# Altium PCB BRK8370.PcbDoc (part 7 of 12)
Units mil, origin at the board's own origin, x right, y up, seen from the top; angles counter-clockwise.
Board outline 8267.72 x 5708.66 mil, 6 copper layers (L1-TOP, L2-GND, L3-PWR, L4-PWR, L5-GND, L6-BOT), stack 68.606 mil thick; 319 components, 516 nets, 2008 pads, 1743 vias.
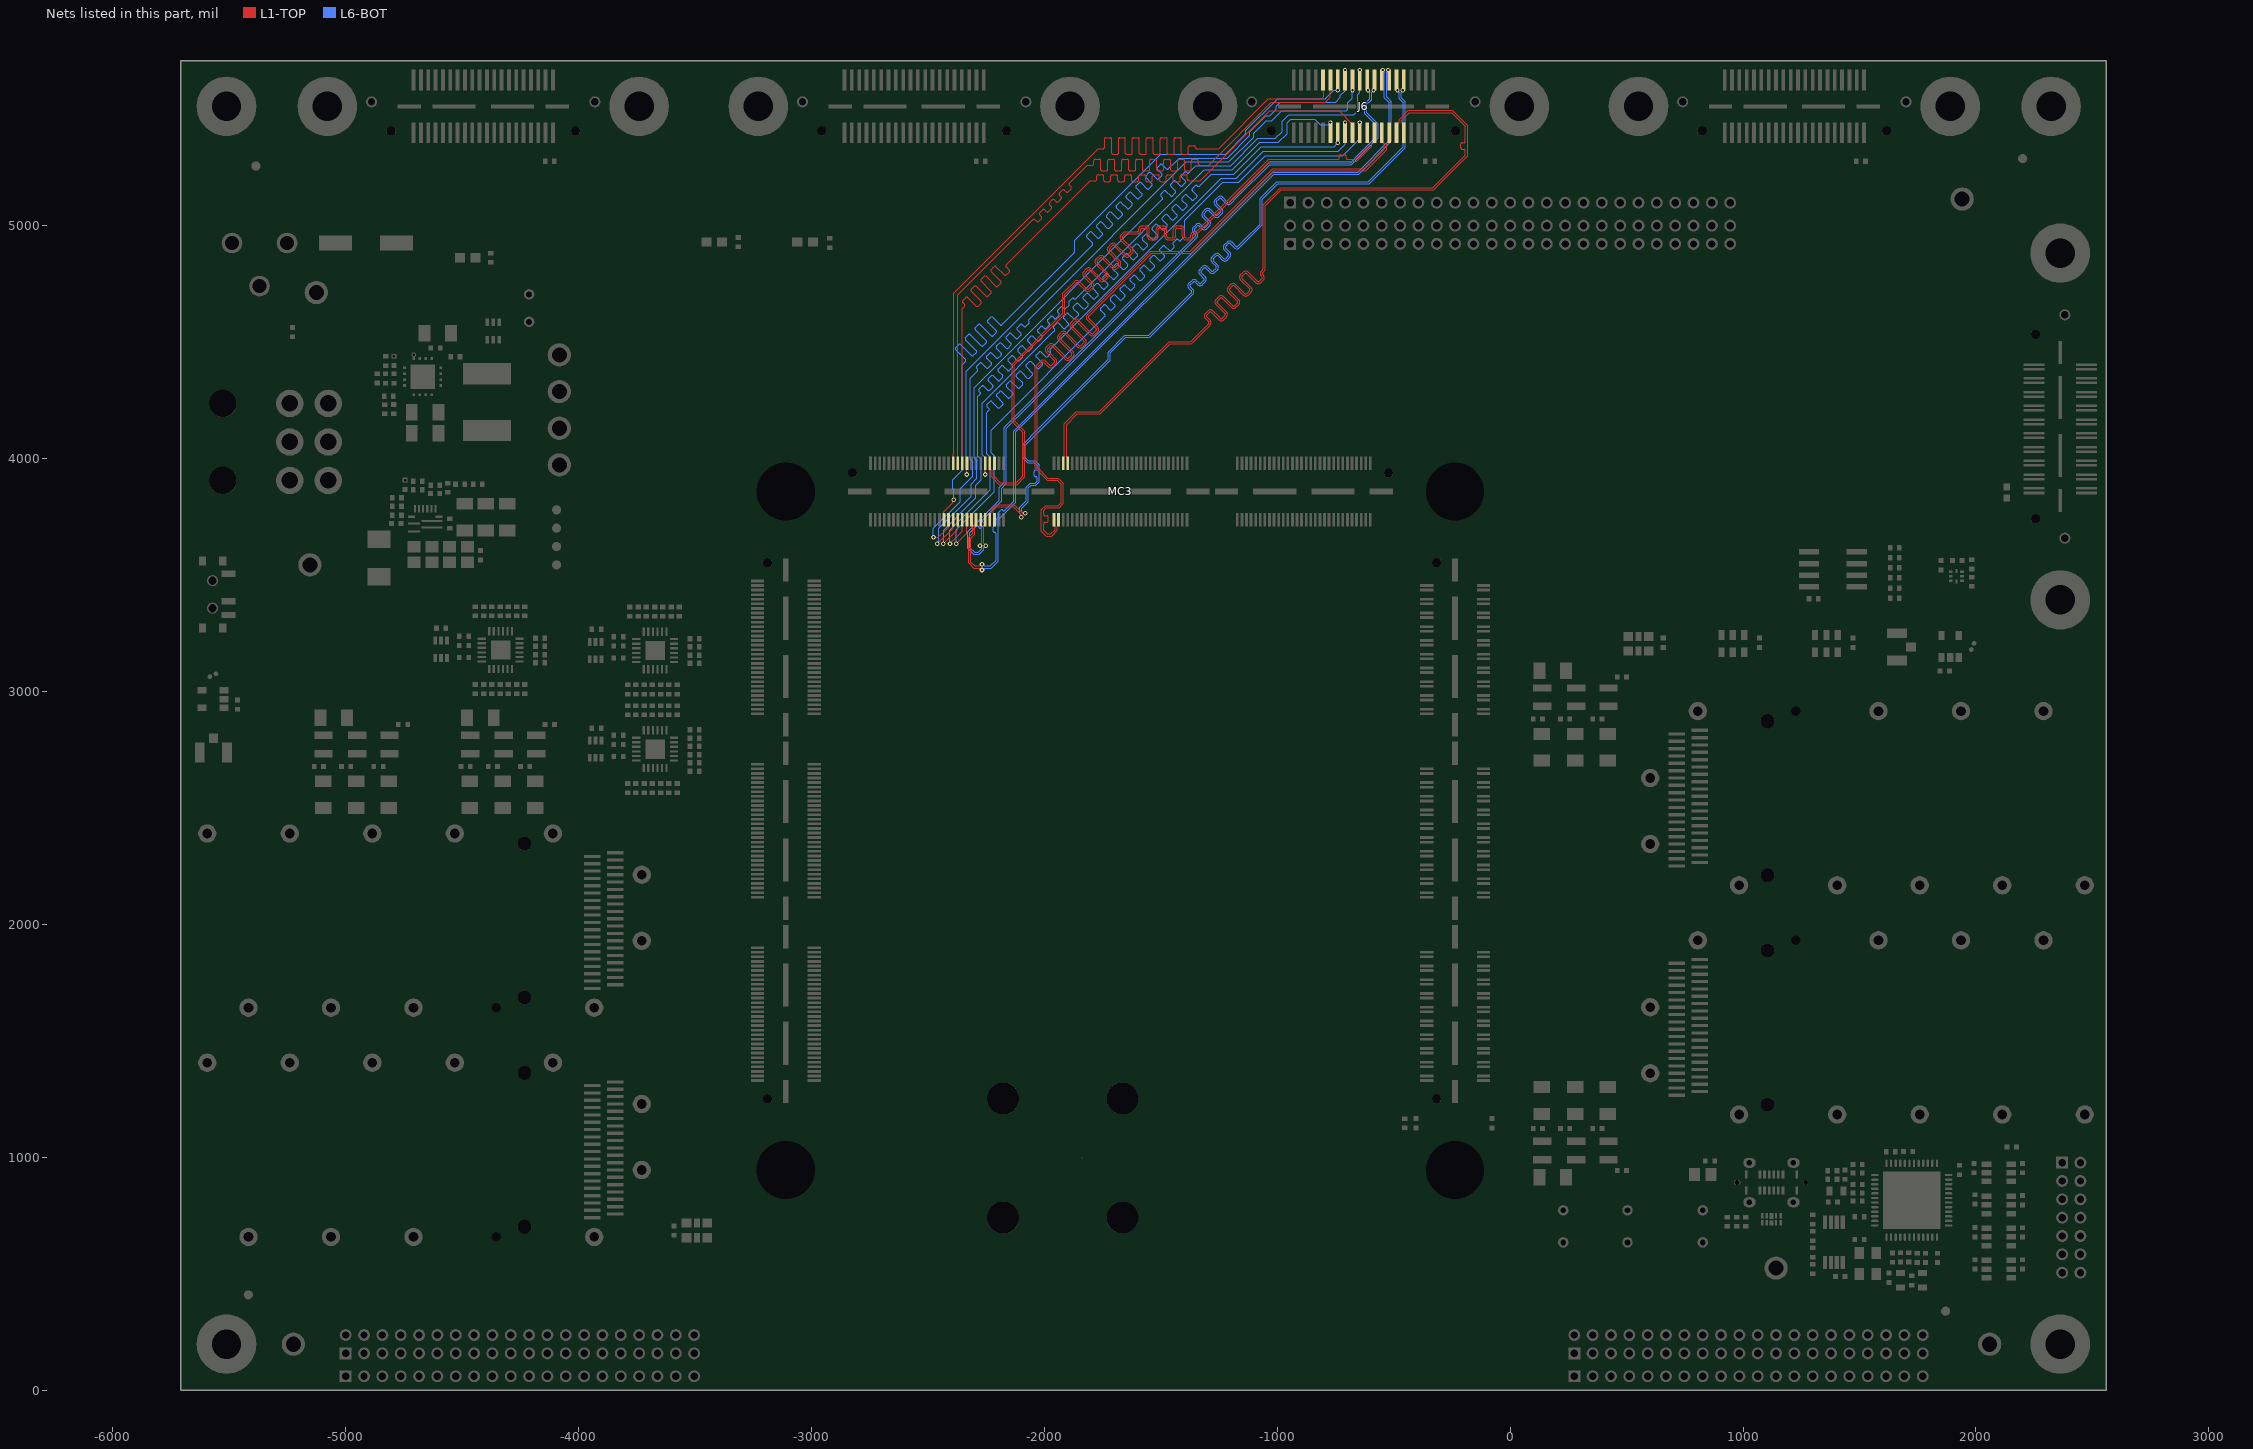
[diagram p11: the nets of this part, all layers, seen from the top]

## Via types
v1: diameter 20, hole 10, L1-TOP to L6-BOT, tented both sides, 957 vias
v2: diameter 18, hole 10, L1-TOP to L6-BOT, tented both sides, 786 vias

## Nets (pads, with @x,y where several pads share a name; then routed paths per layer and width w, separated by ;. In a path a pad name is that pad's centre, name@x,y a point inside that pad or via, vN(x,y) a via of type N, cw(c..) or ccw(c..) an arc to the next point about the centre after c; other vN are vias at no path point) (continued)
PORTC_S4_D2_P: J6.9 MC3.54 | length 3384.1
  L1-TOP w3.3: MC3.54@-2234.25,3736.61 -2234.25,3759.25 -2228.91,3764.59 -2228.91,3781.25 -2208.7,3801.46 -2129.66,3801.46 -2107.96,3779.76 -2094.6,3766.4 -2083.29,3766.4 v1(-2081.67,3764.78)
  L6-BOT w3.3: v1(-2081.67,3764.78) -2083.29,3766.4 -2094.6,3766.4 -2096.62,3768.42 -2096.62,3786.86 -2068.49,3815 -2068.49,3873.81 -2056.6,3885.7 -2036.13,3885.7 -2022.5,3899.33 -2022.5,3972.71 -2039.58,3989.8 -2068.26,3989.8 -2082.68,4004.21 -2082.68,4057.42 -1726.63,4413.47 -1717.64,4422.46 -1717.64,4453.22 -1651.18,4519.68 -1547.9,4519.68 -1523.95,4543.63 -1361.93,4705.65 ccw(c-1372.3,4716.01) -1360.62,4724.87 -1360.62,4725.06 -1361.92,4726.36 -1365.35,4729.79 -1373.12,4737.57 cw(c-1369.12,4741.57) -1373.12,4745.57 -1361.12,4757.58 cw(c-1357.11,4753.58) -1353.11,4757.58 -1341.95,4746.42 ccw(c-1331.56,4756.76) -1321.19,4746.39 -1309.15,4758.43 ccw(c-1319.55,4768.76) -1307.87,4777.62 -1307.87,4777.81 -1326.94,4796.89 cw(c-1322.94,4800.89) -1326.94,4804.89 -1314.93,4816.9 cw(c-1310.93,4812.89) -1306.92,4816.88 ; -1306.9,4816.87 -1289.2,4799.17 ; -1289.2,4799.17 ccw(c-1278.81,4809.51) -1268.44,4799.14 -1256.4,4811.18 ccw(c-1266.8,4821.51) -1255.12,4830.37 -1255.12,4830.56 -1274.19,4849.64 cw(c-1270.19,4853.64) -1274.19,4857.64 -1262.18,4869.65 cw(c-1258.18,4865.64) -1254.17,4869.63 ; -1254.15,4869.62 -1236.45,4851.92 ; -1236.45,4851.92 ccw(c-1226.06,4862.26) -1215.69,4851.89 -1203.65,4863.93 ccw(c-1214.05,4874.26) -1202.37,4883.12 -1202.37,4883.31 -1221.44,4902.39 cw(c-1217.44,4906.39) -1221.44,4910.39 -1209.43,4922.4 cw(c-1205.43,4918.39) -1201.42,4922.38 ; -1201.4,4922.37 -1183.67,4904.64 ccw(c-1173.31,4915.01) -1162.94,4904.64 -1132.22,4935.37 -1064.86,5002.72 -1064.86,5114.06 -998.79,5180.13 -604.76,5180.13 -450.59,5334.31 -450.59,5531.67 -467.97,5549.06 -467.97,5571.97 -460.94,5579.01 v2(-460.94,5581.25)
PORTC_S5_D3_P: J6.10 MC3.65 | length 3565.8
  L1-TOP w3.3: MC3.65@-1919.29,3979.92 -1919.29,4002.56 -1913.95,4007.9 -1913.95,4149.04 -1862.2,4200.79 -1763.78,4200.79 -1463.14,4501.42 -1372.59,4501.42 -1370.08,4503.94 -1294.68,4579.34 ccw(c-1298.68,4583.34) -1294.7,4587.36 ; -1294.7,4587.37 -1308.83,4601.5 cw(c-1298.47,4611.86) -1308.83,4622.23 -1296.79,4634.27 cw(c-1286.46,4623.87) -1276.09,4634.24 -1253.98,4612.12 -1244.26,4602.4 ccw(c-1240.26,4606.41) -1236.26,4602.4 -1224.25,4614.41 ccw(c-1228.25,4618.41) -1224.26,4622.43 -1263.47,4661.63 cw(c-1253.13,4672.03) -1263.5,4682.39 -1251.45,4694.44 cw(c-1241.12,4684.03) -1232.27,4695.72 -1232.08,4695.72 -1191.51,4655.15 ccw(c-1187.51,4659.16) -1183.51,4655.15 -1171.5,4667.16 ccw(c-1175.5,4671.16) -1171.51,4675.18 -1210.72,4714.38 cw(c-1200.38,4724.78) -1210.75,4735.14 -1198.7,4747.19 cw(c-1188.37,4736.78) -1179.52,4748.47 -1179.33,4748.47 -1138.76,4707.9 ccw(c-1134.76,4711.91) -1130.76,4707.9 -1118.75,4719.91 ccw(c-1122.75,4723.91) -1118.76,4727.93 -1157.97,4767.13 cw(c-1147.63,4777.53) -1158,4787.89 -1145.95,4799.94 cw(c-1135.62,4789.53) -1126.77,4801.22 -1126.58,4801.22 -1086.01,4760.65 ccw(c-1082.01,4764.66) -1078.01,4760.65 -1066,4772.66 ccw(c-1070,4776.66) -1066.01,4780.68 -1069.31,4783.97 cw(c-1058.94,4794.34) -1069.31,4804.71 -1064.96,4809.06 -1060.18,4813.83 -1060.18,5088.6 -985.94,5162.84 -331.63,5162.84 -191.79,5302.68 -191.79,5320.82 -191.79,5322.47 ccw(c-197.45,5322.47) -197.45,5328.13 -205.9,5328.13 cw(c-205.9,5333.79) -211.56,5333.79 -211.56,5350.77 cw(c-205.9,5350.77) -205.9,5356.43 -197.45,5356.43 ccw(c-197.45,5362.09) -191.79,5362.09 -191.79,5393.7 -191.79,5425.66 -251.5,5485.38 -433.54,5485.38 -467.87,5451.04 -467.87,5444.04 -465.94,5442.11 -462.97,5442.11 -456.62,5435.76 J6.10@-456.62,5399.01
PORTC_S6_D2_N: J6.11 MC3.56 | length 3384
  L1-TOP w3.3: MC3.56@-2214.57,3736.61 -2214.57,3759.25 -2219.91,3764.59 -2219.91,3777.53 -2204.97,3792.46 -2133.39,3792.46 -2111.69,3770.76 -2100.96,3760.04 -2100.96,3748.72 v1(-2099.35,3747.11)
  L6-BOT w3.3: v1(-2099.35,3747.11) -2100.96,3748.72 -2100.96,3760.04 -2105.62,3764.69 -2105.62,3790.59 -2077.49,3818.72 -2077.49,3877.54 -2060.33,3894.7 -2039.85,3894.7 -2031.5,3903.06 -2031.5,3915.13 -2031.5,3916.78 ccw(c-2037.16,3916.78) -2037.16,3922.44 -2038.13,3922.44 cw(c-2038.13,3928.1) -2043.79,3928.1 -2043.79,3945.08 cw(c-2038.13,3945.08) -2038.13,3950.74 -2037.16,3950.74 ccw(c-2037.16,3956.4) -2031.5,3956.4 -2031.5,3965.05 -2031.5,3968.99 -2043.31,3980.8 -2071.99,3980.8 -2091.68,4000.48 -2091.68,4061.15 -2025.23,4127.6 -1726.64,4426.19 -1726.64,4456.95 -1654.9,4528.68 -1551.62,4528.68 -1530.31,4550 -1368.3,4712.01 ccw(c-1372.3,4716.01) -1368.31,4720.03 -1379.49,4731.2 cw(c-1369.12,4741.57) -1379.49,4751.94 -1367.44,4763.98 cw(c-1357.11,4753.58) -1346.75,4763.94 -1338.97,4756.17 -1335.55,4752.75 ccw(c-1331.56,4756.76) -1327.55,4752.76 -1315.55,4764.76 ccw(c-1319.55,4768.76) -1315.56,4772.78 ; -1333.27,4790.49 -1315.58,4772.8 ; -1333.28,4790.5 cw(c-1322.94,4800.89) -1333.3,4811.25 -1321.26,4823.3 cw(c-1310.93,4812.89) -1302.07,4824.58 -1301.88,4824.58 -1282.8,4805.5 ccw(c-1278.81,4809.51) -1274.8,4805.51 -1262.8,4817.51 ccw(c-1266.8,4821.51) -1262.81,4825.53 ; -1280.52,4843.24 -1262.83,4825.55 ; -1280.53,4843.25 cw(c-1270.19,4853.64) -1280.55,4864 -1268.51,4876.05 cw(c-1258.18,4865.64) -1249.32,4877.33 -1249.13,4877.33 -1230.05,4858.25 ccw(c-1226.06,4862.26) -1222.05,4858.26 -1210.05,4870.26 ccw(c-1214.05,4874.26) -1210.06,4878.28 ; -1227.77,4895.99 -1210.08,4878.3 ; -1227.78,4896 cw(c-1217.44,4906.39) -1227.8,4916.75 -1215.76,4928.8 cw(c-1205.43,4918.39) -1196.57,4930.08 -1196.38,4930.08 -1177.31,4911.01 ccw(c-1173.31,4915.01) -1169.3,4911.01 -1138.58,4941.73 -1073.86,5006.45 -1073.86,5117.79 -1002.51,5189.13 -608.49,5189.13 -459.59,5338.04 -459.59,5527.94 -476.97,5545.33 -476.97,5571.97 -484.01,5579.01 v2(-484.01,5581.25)
PORTC_S7_D3_N: J6.12 MC3.67 | length 3565.9
  L1-TOP w3.3: MC3.67@-1899.61,3979.92 -1899.61,4002.56 -1904.95,4007.9 -1904.95,4145.32 -1858.48,4191.79 -1760.05,4191.79 -1459.42,4492.42 -1368.87,4492.42 -1363.71,4497.57 -1288.31,4572.97 ccw(c-1298.68,4583.34) -1287,4592.19 -1287,4592.39 -1288.3,4593.69 ; -1288.31,4593.71 -1292.63,4598.03 -1302.47,4607.86 cw(c-1298.47,4611.86) -1302.47,4615.86 -1290.46,4627.87 cw(c-1286.46,4623.87) -1282.46,4627.87 -1250.65,4596.06 ccw(c-1240.26,4606.41) -1229.89,4596.04 -1217.85,4608.08 ccw(c-1228.25,4618.41) -1216.57,4627.27 -1216.57,4627.46 -1257.14,4668.03 cw(c-1253.13,4672.03) -1257.13,4676.03 -1245.13,4688.04 cw(c-1241.12,4684.03) -1237.11,4688.02 ; -1237.09,4688.01 -1197.9,4648.82 ccw(c-1187.51,4659.16) -1177.14,4648.79 -1165.1,4660.83 ccw(c-1175.5,4671.16) -1163.82,4680.02 -1163.82,4680.21 -1204.39,4720.78 cw(c-1200.38,4724.78) -1204.38,4728.78 -1192.38,4740.79 cw(c-1188.37,4736.78) -1184.36,4740.77 ; -1184.34,4740.76 -1145.15,4701.57 ccw(c-1134.76,4711.91) -1124.39,4701.54 -1112.35,4713.58 ccw(c-1122.75,4723.91) -1111.07,4732.77 -1111.07,4732.96 -1151.64,4773.53 cw(c-1147.63,4777.53) -1151.63,4781.53 -1139.63,4793.54 cw(c-1135.62,4789.53) -1131.61,4793.52 ; -1131.59,4793.51 -1092.4,4754.32 ccw(c-1082.01,4764.66) -1071.64,4754.29 -1059.6,4766.33 ccw(c-1070,4776.66) -1058.32,4785.52 -1058.32,4785.71 -1062.95,4790.34 cw(c-1058.94,4794.34) -1062.95,4798.34 -1058.6,4802.69 -1051.18,4810.11 -1051.18,5084.87 -982.21,5153.84 -327.9,5153.84 -182.79,5298.96 -182.79,5429.39 -247.77,5494.38 -437.26,5494.38 -476.87,5454.77 -476.87,5444.04 -478.8,5442.11 -481.77,5442.11 -488.12,5435.76 J6.12@-488.12,5399.01
PORTC_S8_D4_P: J6.13 MC3.46 | length 3383.9
  L1-TOP w3.3: MC3.46@-2312.99,3736.61 -2312.99,3713.98 -2307.65,3708.63 -2307.65,3679.15 -2325.65,3661.15 -2325.65,3551.65 -2303.49,3529.49 -2278,3529.49 -2270,3521.49 v1(-2267.72,3521.49)
  L6-BOT w3.3: v1(-2267.72,3521.49) -2265.43,3521.49 -2257.43,3529.49 -2227.84,3529.49 -2198.54,3558.8 -2198.54,3735.96 -2152.22,3782.28 -2122.45,3812.05 -2122.45,4113.95 -1015.62,5220.78 -650.73,5220.78 -509.64,5361.87 -509.64,5531.67 -530.87,5552.9 -530.87,5658.69 -523.84,5665.72 v2(-523.84,5667.97)
PORTC_S9_D5_P: J6.14 MC3.62 | length 3567.3
  L1-TOP w3.3: -1966.11,4482.48 ccw(c-1970.12,4478.49) -1974.13,4482.49 -1986.13,4470.48 ccw(c-1982.13,4466.48) -1986.14,4462.48 -1975.21,4451.56 -1950.34,4426.69 cw(c-1960.71,4416.32) -1950.31,4405.99 -1962.35,4393.95 cw(c-1972.71,4404.31) -1983.08,4393.95 -2001.19,4412.06 ccw(c-2005.2,4408.06) -2009.2,4412.06 -2024.23,4397.03 -2030.33,4390.93 -2030.33,3961.81 -1984.72,3916.2 -1941.25,3916.2 -1919.01,3893.96 -1919.01,3806.83 -1936.75,3789.09 -1990.85,3789.09 -2003.45,3776.49 -2003.45,3768.4 -2003.45,3760.4 ccw(c-1997.79,3760.4) -1997.79,3754.74 -1989.34,3754.74 cw(c-1989.34,3749.08) -1983.68,3749.08 -1983.68,3732.1 cw(c-1989.34,3732.1) -1989.34,3726.44 -1997.79,3726.44 ccw(c-1997.79,3720.78) -2003.45,3720.78 -2003.45,3690.83 -1988.66,3676.04 -1971.97,3676.04 -1953.32,3694.7 -1953.32,3708.63 -1958.66,3713.98 MC3.62@-1958.66,3736.61 ; -1966.09,4482.46 -1909.58,4425.95 ccw(c-1899.19,4436.28) -1888.82,4425.92 -1876.78,4437.96 ccw(c-1887.18,4448.29) -1875.49,4457.15 -1875.49,4457.34 -1933.39,4515.23 cw(c-1929.38,4519.23) -1933.38,4523.23 -1921.38,4535.24 cw(c-1917.37,4531.24) -1913.36,4535.23 ; -1913.34,4535.21 -1856.83,4478.7 ccw(c-1846.44,4489.03) -1836.07,4478.67 -1824.03,4490.71 ccw(c-1834.43,4501.04) -1822.74,4509.9 -1822.74,4510.09 -1880.64,4567.98 cw(c-1876.63,4571.98) -1880.63,4575.98 -1868.63,4587.99 cw(c-1864.62,4583.99) -1860.61,4587.98 ; -1860.59,4587.96 -1804.08,4531.45 ccw(c-1793.69,4541.78) -1783.32,4531.42 -1771.28,4543.46 ccw(c-1781.68,4553.79) -1769.99,4562.65 -1769.99,4562.84 -1810.21,4603.05 cw(c-1806.2,4607.05) -1810.21,4611.05 -1805.86,4615.4 -1539.37,4881.89 -1369.14,4881.89 -1015.89,5235.14 -620.62,5235.14 -530.87,5324.89 -530.87,5353.98 -528.94,5355.91 -525.97,5355.91 -519.62,5362.26 J6.14@-519.62,5399.01
PORTC_S10_D4_N: J6.15 MC3.48 | length 3383.9
  L1-TOP w3.3: MC3.48@-2293.31,3736.61 -2293.31,3713.98 -2298.65,3708.63 -2298.65,3675.42 -2316.65,3657.42 -2316.65,3555.38 -2299.77,3538.49 -2278,3538.49 -2270,3546.49 v1(-2267.72,3546.49)
  L6-BOT w3.3: v1(-2267.72,3546.49) -2265.43,3546.49 -2257.43,3538.49 -2231.57,3538.49 -2207.54,3562.53 -2207.54,3675.26 -2207.54,3676.91 ccw(c-2213.2,3676.91) -2213.2,3682.57 -2214.26,3682.57 cw(c-2214.26,3688.23) -2219.92,3688.23 -2219.92,3705.21 cw(c-2214.26,3705.21) -2214.26,3710.87 -2213.2,3710.87 ccw(c-2213.2,3716.53) -2207.54,3716.53 -2207.54,3732.98 -2207.54,3739.69 -2198.75,3748.47 -2197.59,3749.64 ccw(c-2201.59,3753.64) -2197.59,3757.65 -2198.24,3758.3 cw(c-2194.24,3762.3) -2198.24,3766.31 -2186.24,3778.31 cw(c-2182.23,3774.31) -2178.23,3778.31 -2177.58,3777.66 ccw(c-2173.57,3781.66) -2169.57,3777.66 -2158.59,3788.64 -2131.45,3815.77 -2131.45,4117.68 -1019.35,5229.78 -654.45,5229.78 -518.64,5365.59 -518.64,5527.94 -539.87,5549.17 -539.87,5658.69 -546.91,5665.72 v2(-546.91,5667.97)
PORTC_S11_D5_N: J6.16 MC3.64 | length 3567.3
  L1-TOP w3.3: MC3.64@-1938.98,3736.61 -1938.98,3713.98 -1944.32,3708.63 -1944.32,3690.97 -1968.25,3667.04 -1992.38,3667.04 -2012.45,3687.1 -2012.45,3780.21 -1994.57,3798.09 -1940.48,3798.09 -1928.01,3810.56 -1928.01,3890.23 -1944.98,3907.2 -1988.45,3907.2 -2039.33,3958.08 -2039.33,4394.66 -2030.6,4403.39 -2015.56,4418.43 cw(c-2005.2,4408.06) -1994.83,4418.43 -1976.72,4400.31 ccw(c-1972.71,4404.31) -1968.71,4400.31 -1956.71,4412.32 ccw(c-1960.71,4416.32) -1956.71,4420.32 -1992.47,4456.09 cw(c-1982.13,4466.48) -1992.5,4476.85 -1980.45,4488.89 cw(c-1970.12,4478.49) -1961.27,4490.17 -1961.08,4490.17 -1903.18,4432.28 ccw(c-1899.19,4436.28) -1895.18,4432.28 -1883.18,4444.29 ccw(c-1887.18,4448.29) -1883.19,4452.3 ; -1883.21,4452.32 -1939.72,4508.84 cw(c-1929.38,4519.23) -1939.75,4529.6 -1927.7,4541.64 cw(c-1917.37,4531.24) -1908.52,4542.92 -1908.33,4542.92 -1850.43,4485.03 ccw(c-1846.44,4489.03) -1842.43,4485.03 -1830.43,4497.04 ccw(c-1834.43,4501.04) -1830.44,4505.05 ; -1830.46,4505.07 -1886.97,4561.59 cw(c-1876.63,4571.98) -1887,4582.35 -1874.95,4594.39 cw(c-1864.62,4583.99) -1855.77,4595.67 -1855.58,4595.67 -1797.68,4537.78 ccw(c-1793.69,4541.78) -1789.68,4537.78 -1777.68,4549.79 ccw(c-1781.68,4553.79) -1777.69,4557.8 ; -1777.71,4557.82 -1816.57,4596.69 cw(c-1806.2,4607.05) -1816.57,4617.42 -1812.22,4621.77 -1543.1,4890.89 -1372.87,4890.89 -1019.61,5244.14 -624.35,5244.14 -539.87,5328.62 -539.87,5353.98 -541.8,5355.91 -544.77,5355.91 -551.12,5362.26 J6.16@-551.12,5399.01
PORTC_S12_D6_P: J6.17 MC3.50 | length 3384.2
  L1-TOP w3.3: v1(-2276.28,3625.98) -2276.28,3628.27 -2268.28,3636.27 -2268.28,3665.35 -2268.28,3708.63 -2273.62,3713.98 MC3.50@-2273.62,3736.61
  L6-BOT w3.3: v1(-2276.28,3625.98) -2276.28,3623.7 -2268.28,3615.7 -2268.28,3612.84 -2283.82,3597.3 -2299.68,3597.3 -2320.02,3617.64 -2320.02,3665.35 -2320.02,3681.41 -2314.12,3687.31 -2292.94,3708.49 cw(c-2288.94,3704.48) -2284.94,3708.49 -2278.97,3702.52 ccw(c-2274.97,3706.52) -2270.97,3702.52 -2258.96,3714.52 ccw(c-2262.96,3718.53) -2258.96,3722.53 -2264.93,3728.5 cw(c-2260.93,3732.5) -2264.93,3736.5 -2252.68,3748.75 -2183.68,3817.75 -2183.68,3872.87 -2163.1,3893.44 -2163.1,4055.12 -2163.1,4130.79 -1396.95,4896.95 -1345.57,4948.33 ccw(c-1355.93,4958.69) -1344.25,4967.55 -1344.25,4967.74 -1345.55,4969.04 ; -1345.57,4969.06 -1348.3,4971.79 -1354.53,4978.02 cw(c-1350.53,4982.02) -1354.53,4986.02 -1342.52,4998.03 cw(c-1338.52,4994.03) -1334.52,4998.03 -1323.21,4986.72 ccw(c-1312.82,4997.07) -1302.45,4986.7 -1290.41,4998.74 ccw(c-1300.81,5009.07) -1289.13,5017.93 -1289.13,5018.12 -1313.81,5042.8 cw(c-1309.8,5046.8) -1313.8,5050.8 -1301.8,5062.81 cw(c-1297.8,5058.8) -1293.78,5062.79 ; -1293.76,5062.78 -1270.47,5039.48 ccw(c-1260.07,5049.82) -1249.7,5039.45 -1237.66,5051.49 ccw(c-1248.06,5061.82) -1236.38,5070.68 -1236.38,5070.87 -1261.06,5095.55 cw(c-1257.05,5099.55) -1261.05,5103.55 -1249.05,5115.56 cw(c-1245.05,5111.55) -1241.03,5115.54 ; -1241.01,5115.53 -1220.06,5094.57 ccw(c-1209.69,5104.93) -1199.32,5094.57 -1168.6,5125.29 -1032.46,5261.43 -681.54,5261.43 -634.9,5308.07 -565.8,5377.16 -565.8,5434.29 -615.22,5483.7 -615.22,5520.07 -593.97,5541.32 -593.97,5571.97 -586.94,5579.01 v2(-586.94,5581.25)
PORTC_S13_D7_P: J6.18 MC3.53 | length 3566.7
  L1-TOP w3.3: MC3.53@-2234.25,3979.92 -2234.25,3957.28 -2228.91,3951.94 -2228.91,3923.25 -2193.17,3887.51 -2117.16,3887.51 -2084.16,3920.51 -2084.16,4116.58 -2110.24,4142.65 -2129.92,4162.33 -2129.92,4401.57 -1912.26,4619.24 -1912.26,4704.72 -1902.98,4714 -1863.92,4753.07 cw(c-1859.91,4749.07) -1855.89,4753.05 -1824.76,4721.92 ccw(c-1814.39,4732.29) -1804.03,4721.92 -1791.99,4733.96 ccw(c-1802.39,4744.29) -1792.02,4754.66 -1815.04,4777.68 -1825.15,4787.79 cw(c-1821.15,4791.79) -1825.15,4795.79 -1813.14,4807.8 cw(c-1809.14,4803.79) -1805.13,4807.79 -1761.01,4763.67 ccw(c-1750.61,4774) -1740.25,4763.64 -1728.2,4775.68 ccw(c-1738.61,4786.01) -1726.92,4794.86 -1726.92,4795.06 -1772.4,4840.54 cw(c-1768.4,4844.54) -1772.4,4848.54 -1760.39,4860.55 cw(c-1756.39,4856.54) -1752.38,4860.54 -1708.26,4816.42 ccw(c-1697.86,4826.75) -1687.5,4816.39 -1675.45,4828.43 ccw(c-1685.86,4838.76) -1674.17,4847.61 -1674.17,4847.81 -1719.65,4893.29 cw(c-1715.65,4897.29) -1719.65,4901.29 -1707.64,4913.3 cw(c-1703.64,4909.29) -1699.63,4913.29 -1655.51,4869.17 ccw(c-1645.11,4879.5) -1634.75,4869.14 -1622.7,4881.18 ccw(c-1633.11,4891.51) -1621.42,4900.36 -1621.42,4900.56 -1664.92,4944.06 cw(c-1660.92,4948.06) -1664.92,4952.06 -1660.57,4956.41 -1652.42,4964.57 -1629.92,4964.57 -1600.75,4964.57 ccw(c-1600.75,4979.23) -1586.09,4979.23 -1586.09,4983.91 cw(c-1580.43,4983.91) -1580.43,4989.57 -1563.45,4989.57 cw(c-1563.45,4983.91) -1557.79,4983.91 -1557.79,4954.23 ccw(c-1543.13,4954.23) -1543.13,4939.57 -1526.15,4939.57 ccw(c-1526.15,4954.23) -1511.49,4954.23 -1511.49,4983.91 cw(c-1505.83,4983.91) -1505.83,4989.57 -1488.85,4989.57 cw(c-1488.85,4983.91) -1483.19,4983.91 -1483.19,4954.23 ccw(c-1468.53,4954.23) -1468.53,4939.57 -1451.55,4939.57 ccw(c-1451.55,4954.23) -1436.89,4954.23 -1436.89,4983.91 cw(c-1431.23,4983.91) -1431.23,4989.57 -1414.25,4989.57 cw(c-1414.25,4983.91) -1408.59,4983.91 -1408.59,4954.23 ccw(c-1393.93,4954.23) -1393.93,4939.57 -1376.95,4939.57 ccw(c-1376.95,4954.23) -1362.29,4954.23 -1362.29,4958.91 cw(c-1356.63,4958.91) -1356.63,4964.57 -1350.48,4964.57 -1343.95,4964.57 -1032.72,5275.79 -658.71,5275.79 -593.87,5340.63 -593.87,5353.98 -591.94,5355.91 -588.97,5355.91 -582.62,5362.26 J6.18@-582.62,5399.01
PORTC_S14_D6_N: J6.19 MC3.52 | length 3384.2
  L1-TOP w3.3: MC3.52@-2253.94,3736.61 -2253.94,3713.98 -2259.28,3708.63 -2259.28,3665.35 -2259.28,3636.27 -2251.28,3628.27 v1(-2251.28,3625.98)
  L6-BOT w3.3: v1(-2251.28,3625.98) -2251.28,3623.7 -2259.28,3615.7 -2259.28,3609.11 -2280.09,3588.3 -2303.41,3588.3 -2329.02,3613.92 -2329.02,3665.35 -2329.02,3685.13 -2192.68,3821.48 -2192.68,3876.6 -2172.1,3897.17 -2172.1,4055.12 -2172.1,4134.52 -1403.31,4903.31 -1351.93,4954.69 ccw(c-1355.93,4958.69) -1351.95,4962.71 ; -1351.96,4962.72 -1360.89,4971.66 cw(c-1350.53,4982.02) -1360.89,4992.39 -1348.85,5004.43 cw(c-1338.52,4994.03) -1328.15,5004.4 -1320.28,4996.52 -1316.82,4993.06 ccw(c-1312.82,4997.07) -1308.82,4993.06 -1296.81,5005.07 ccw(c-1300.81,5009.07) -1296.82,5013.09 ; -1296.84,5013.1 -1320.14,5036.4 cw(c-1309.8,5046.8) -1320.17,5057.16 -1308.12,5069.21 cw(c-1297.8,5058.8) -1288.94,5070.49 -1288.75,5070.49 -1264.07,5045.81 ccw(c-1260.07,5049.82) -1256.07,5045.81 -1244.06,5057.82 ccw(c-1248.06,5061.82) -1244.07,5065.84 ; -1244.09,5065.85 -1267.39,5089.15 cw(c-1257.05,5099.55) -1267.42,5109.91 -1255.37,5121.96 cw(c-1245.05,5111.55) -1236.19,5123.24 -1236,5123.24 -1213.69,5100.93 ccw(c-1209.69,5104.93) -1205.69,5100.93 -1174.96,5131.66 -1036.19,5270.43 -685.26,5270.43 -647.62,5308.07 -574.8,5380.89 -574.8,5430.56 -624.22,5479.98 -624.22,5523.8 -602.97,5545.04 -602.97,5571.97 -610.01,5579.01 v2(-610.01,5581.25)
PORTC_S15_D7_N: J6.20 MC3.55 | length 3566.7
  L1-TOP w3.3: MC3.55@-2214.57,3979.92 -2214.57,3957.28 -2219.91,3951.94 -2219.91,3926.98 -2189.44,3896.51 -2120.89,3896.51 -2093.16,3924.24 -2093.16,4112.85 -2110.24,4129.92 -2138.92,4158.61 -2138.92,4405.3 -1921.26,4622.96 -1921.26,4708.45 -1909.34,4720.37 -1870.28,4759.43 cw(c-1859.91,4749.07) -1851.06,4760.75 -1850.86,4760.75 -1849.56,4759.45 ; -1849.55,4759.43 -1840.04,4749.93 -1818.4,4728.28 ccw(c-1814.39,4732.29) -1810.39,4728.28 -1798.39,4740.29 ccw(c-1802.39,4744.29) -1798.39,4748.29 -1831.49,4781.4 cw(c-1821.15,4791.79) -1831.51,4802.15 -1819.47,4814.2 cw(c-1809.14,4803.79) -1800.29,4815.48 -1800.09,4815.48 -1754.61,4770 ccw(c-1750.61,4774) -1746.61,4770 -1734.6,4782.01 ccw(c-1738.61,4786.01) -1734.61,4790.02 -1778.73,4834.14 ; -1778.74,4834.15 cw(c-1768.4,4844.54) -1778.76,4854.9 -1766.72,4866.95 cw(c-1756.39,4856.54) -1747.54,4868.23 -1747.34,4868.23 -1701.86,4822.75 ccw(c-1697.86,4826.75) -1693.86,4822.75 -1681.85,4834.76 ccw(c-1685.86,4838.76) -1681.86,4842.77 -1725.98,4886.89 ; -1725.99,4886.9 cw(c-1715.65,4897.29) -1726.01,4907.65 -1713.97,4919.7 cw(c-1703.64,4909.29) -1694.79,4920.98 -1694.59,4920.98 -1649.11,4875.5 ccw(c-1645.11,4879.5) -1641.11,4875.5 -1629.1,4887.51 ccw(c-1633.11,4891.51) -1629.11,4895.52 -1671.29,4937.69 cw(c-1660.92,4948.06) -1671.29,4958.43 -1666.94,4962.78 -1656.15,4973.57 -1629.92,4973.57 -1600.75,4973.57 ccw(c-1600.75,4979.23) -1595.09,4979.23 -1595.09,4983.91 cw(c-1580.43,4983.91) -1580.43,4998.57 -1563.45,4998.57 cw(c-1563.45,4983.91) -1548.79,4983.91 -1548.79,4954.23 ccw(c-1543.13,4954.23) -1543.13,4948.57 -1526.15,4948.57 ccw(c-1526.15,4954.23) -1520.49,4954.23 -1520.49,4983.91 cw(c-1505.83,4983.91) -1505.83,4998.57 -1488.85,4998.57 cw(c-1488.85,4983.91) -1474.19,4983.91 -1474.19,4954.23 ccw(c-1468.53,4954.23) -1468.53,4948.57 -1451.55,4948.57 ccw(c-1451.55,4954.23) -1445.89,4954.23 -1445.89,4983.91 cw(c-1431.23,4983.91) -1431.23,4998.57 -1414.25,4998.57 cw(c-1414.25,4983.91) -1399.59,4983.91 -1399.59,4954.23 ccw(c-1393.93,4954.23) -1393.93,4948.57 -1376.95,4948.57 ccw(c-1376.95,4954.23) -1371.29,4954.23 -1371.29,4958.91 cw(c-1356.63,4958.91) -1356.63,4973.57 -1350.48,4973.57 -1347.68,4973.57 -1036.45,5284.79 -775.59,5284.79 -738.64,5284.79 ccw(c-738.64,5290.45) -732.98,5290.45 -732.98,5298.9 cw(c-727.32,5298.9) -727.32,5304.56 -710.34,5304.56 cw(c-710.34,5298.9) -704.68,5298.9 -704.68,5290.45 ccw(c-699.02,5290.45) -699.02,5284.79 -669.07,5284.79 -662.44,5284.79 -602.87,5344.36 -602.87,5353.98 -604.8,5355.91 -607.77,5355.91 -614.12,5362.26 J6.20@-614.12,5399.01
PORTC_S16: J6.21 MC3.38 | length 3382.7
  L1-TOP w4.96: v1(-2460.63,3633.86) -2458.97,3633.86 -2391.73,3701.1 MC3.38@-2391.73,3736.61
  L6-BOT w4.96: v1(-2460.63,3633.86) -2460.63,3635.76 -2452.76,3643.64 -2452.76,3700.42 -2314.96,3838.22 -2314.96,3889.76 -2290.12,3914.6 -2290.12,3990.75 -2291.34,3991.97 -2291.34,3992.13 -2302.12,4002.9 -2302.12,4303.87 -1495.19,5110.79 -1493.43,5112.55 ccw(c-1497.67,5116.79) -1493.43,5121.02 -1499.22,5126.81 cw(c-1494.98,5131.04) -1499.22,5135.28 -1486.51,5147.99 cw(c-1482.27,5143.76) -1478.03,5147.99 -1458.17,5128.13 ccw(c-1453.93,5132.37) -1449.69,5128.13 -1436.98,5140.84 ccw(c-1441.22,5145.08) -1436.98,5149.32 -1456.84,5169.18 cw(c-1452.61,5173.42) -1456.84,5177.66 -1444.13,5190.37 cw(c-1439.89,5186.13) -1435.66,5190.37 -1415.79,5170.51 ccw(c-1411.56,5174.74) -1407.32,5170.51 -1394.61,5183.22 ccw(c-1398.85,5187.46) -1394.61,5191.69 -1410.88,5207.97 cw(c-1406.65,5212.21) -1410.88,5216.45 -1398.17,5229.16 cw(c-1393.93,5224.92) -1389.7,5229.16 -1387.5,5226.96 ccw(c-1383.26,5231.2) -1379.02,5226.96 -1360.08,5245.91 -1349.79,5256.2 -1200.5,5256.2 -1082.68,5374.02 -1007.87,5374.02 -979.47,5402.42 -979.47,5448.57 -951.66,5476.38 -672.13,5476.38 -655.17,5493.33 -655.17,5562.41 -645.72,5571.86 v2(-645.72,5667.97)
PORTC_S17: J6.22 MC3.44 | length 3382.7
  L1-TOP w4.96: v1(-2377.95,3633.86) -2332.68,3679.13 MC3.44@-2332.68,3736.61
  L6-BOT w4.96: v1(-2377.95,3633.86) -2377.95,3694.17 -2215.32,3856.8 -2215.32,4012.07 -2228.35,4025.09 -2228.35,4122.05 -1742.13,4608.27 -1740.37,4610.02 ccw(c-1744.61,4614.26) -1740.37,4618.5 -1758.57,4636.7 cw(c-1754.33,4640.93) -1758.57,4645.17 -1745.86,4657.88 cw(c-1741.62,4653.65) -1737.38,4657.88 -1718.67,4639.17 ccw(c-1714.44,4643.41) -1710.2,4639.17 -1697.49,4651.89 ccw(c-1701.72,4656.12) -1697.49,4660.36 -1716.2,4679.07 cw(c-1711.96,4683.31) -1716.2,4687.54 -1703.48,4700.26 cw(c-1699.25,4696.02) -1695.01,4700.26 -1676.3,4681.55 ccw(c-1672.06,4685.78) -1667.82,4681.55 -1655.11,4694.26 ccw(c-1659.35,4698.5) -1655.11,4702.73 -1673.82,4721.44 cw(c-1669.58,4725.68) -1673.82,4729.92 -1661.11,4742.63 cw(c-1656.87,4738.39) -1652.63,4742.63 -1633.92,4723.92 ccw(c-1629.69,4728.16) -1625.45,4723.92 -1612.74,4736.63 ccw(c-1616.97,4740.87) -1612.74,4745.11 -1631.45,4763.82 cw(c-1627.21,4768.06) -1631.45,4772.29 -1618.73,4785 cw(c-1614.5,4780.77) -1610.26,4785 -1591.55,4766.3 ccw(c-1587.31,4770.53) -1583.08,4766.3 -1570.36,4779.01 ccw(c-1574.6,4783.24) -1570.36,4787.48 -1589.07,4806.19 cw(c-1584.84,4810.43) -1589.07,4814.67 -1576.36,4827.38 cw(c-1572.12,4823.14) -1567.89,4827.38 -1549.18,4808.67 ccw(c-1544.94,4812.91) -1540.7,4808.67 -1527.99,4821.38 ccw(c-1532.23,4825.62) -1527.99,4829.86 -1546.7,4848.57 cw(c-1542.46,4852.8) -1546.7,4857.04 -1533.99,4869.75 cw(c-1529.75,4865.52) -1525.51,4869.75 -1506.8,4851.04 ccw(c-1502.56,4855.28) -1498.33,4851.04 -1485.62,4863.76 ccw(c-1489.85,4867.99) -1485.62,4872.23 -1504.32,4890.94 cw(c-1500.09,4895.18) -1504.32,4899.41 -1491.61,4912.13 cw(c-1487.38,4907.89) -1483.14,4912.13 -1464.43,4893.42 ccw(c-1460.19,4897.65) -1455.95,4893.42 -1443.24,4906.13 ccw(c-1447.48,4910.37) -1443.24,4914.6 -1447.09,4918.45 cw(c-1442.85,4922.69) -1447.09,4926.92 -1434.37,4939.64 cw(c-1430.14,4935.4) -1425.9,4939.64 -1422.57,4936.3 ccw(c-1418.33,4940.54) -1414.09,4936.3 -1407.48,4942.91 -1397.64,4952.76 -1397.64,5023.25 -1234.35,5186.55 -1165.82,5186.55 -1052.12,5300.25 -719.44,5300.25 -645.72,5373.96 v2(-645.72,5442.37)
PORTC_S18: J6.23 MC3.36 | length 3382.7
  L1-TOP w4.96: v1(-2476.38,3661.42) -2455.4,3661.42 -2411.42,3705.4 MC3.36@-2411.42,3736.61
  L6-BOT w4.96: v1(-2476.38,3661.42) -2476.38,3700.79 -2362.2,3814.96 -2362.2,3868.99 -2307.09,3924.11 -2307.09,3983.73 -2319.08,3995.72 -2319.08,4344.14 -2288.8,4374.41 -2287.05,4376.17 ccw(c-2291.29,4380.41) -2287.05,4384.64 -2290.49,4388.08 cw(c-2286.25,4392.32) -2290.49,4396.56 -2277.78,4409.27 cw(c-2273.54,4405.03) -2269.3,4409.27 -2249.24,4389.21 ccw(c-2245,4393.45) -2240.77,4389.21 -2228.05,4401.92 ccw(c-2232.29,4406.16) -2228.05,4410.39 -2248.11,4430.46 cw(c-2243.88,4434.69) -2248.11,4438.93 -2235.4,4451.64 cw(c-2231.17,4447.41) -2226.93,4451.64 -2206.87,4431.58 ccw(c-2202.63,4435.82) -2198.39,4431.58 -2185.68,4444.29 ccw(c-2189.92,4448.53) -2185.68,4452.77 -2205.74,4472.83 cw(c-2201.5,4477.07) -2205.74,4481.31 -2193.03,4494.02 cw(c-2188.79,4489.78) -2184.55,4494.02 -2164.49,4473.96 ccw(c-2160.25,4478.19) -2156.02,4473.96 -2143.3,4486.67 ccw(c-2147.54,4490.91) -2143.3,4495.14 ; -2143.3,4495.14 -2163.37,4515.2 cw(c-2159.13,4519.44) -2163.37,4523.68 -2150.65,4536.39 cw(c-2146.42,4532.15) -2142.18,4536.39 -2122.12,4516.33 ccw(c-2117.88,4520.57) -2113.64,4516.33 -2100.93,4529.04 ccw(c-2105.17,4533.28) -2100.93,4537.52 -2116.44,4553.03 cw(c-2112.2,4557.26) -2116.44,4561.5 -2103.73,4574.21 cw(c-2099.49,4569.98) -2095.25,4574.21 -2087.89,4566.85 ccw(c-2083.65,4571.09) -2079.42,4566.85 -2066.7,4579.56 ccw(c-2070.94,4583.8) -2066.7,4588.04 cw(c-2062.47,4592.28) -2066.7,4596.51 -2021.57,4641.65 -1390.06,5273.16 -1207.52,5273.16 -1100.58,5380.1 -1100.58,5395.49 -1046.72,5449.34 -1022.67,5449.34 -979.88,5492.13 -704.72,5492.13 -696.85,5500 -696.85,5527.56 -677.22,5547.19 v2(-677.22,5581.25)
PORTC_S19: J6.24 MC3.41 | length 3564.2
  L1-TOP w4.96: MC3.41@-2352.36,3979.92 -2352.36,4643.7 -2344.39,4651.68 -2342.63,4653.43 ccw(c-2346.87,4657.67) -2342.63,4661.91 -2350.13,4669.41 cw(c-2345.9,4673.65) -2350.13,4677.88 -2337.42,4690.6 cw(c-2333.18,4686.36) -2328.95,4690.6 -2292.92,4654.57 ccw(c-2288.68,4658.81) -2284.45,4654.57 -2271.73,4667.28 ccw(c-2275.97,4671.52) -2271.73,4675.76 -2313.87,4717.89 cw(c-2309.63,4722.13) -2313.87,4726.36 -2301.15,4739.08 cw(c-2296.92,4734.84) -2292.68,4739.08 -2250.55,4696.94 ccw(c-2246.31,4701.18) -2242.07,4696.94 -2229.36,4709.66 ccw(c-2233.6,4713.89) -2229.36,4718.13 -2271.49,4760.26 cw(c-2267.25,4764.5) -2271.49,4768.74 -2258.78,4781.45 cw(c-2254.54,4777.21) -2250.3,4781.45 -2208.17,4739.32 ccw(c-2203.94,4743.56) -2199.7,4739.32 -2186.99,4752.03 ccw(c-2191.22,4756.27) -2186.99,4760.51 -2229.12,4802.64 cw(c-2224.88,4806.87) -2229.12,4811.11 -2216.4,4823.82 cw(c-2212.17,4819.59) -2207.93,4823.82 -2172.14,4788.03 ccw(c-2167.9,4792.27) -2163.66,4788.03 -2150.95,4800.74 ccw(c-2155.19,4804.98) -2150.95,4809.22 -2164.66,4822.93 cw(c-2160.42,4827.17) -2164.66,4831.4 -2129.92,4866.14 -1803.15,5192.91 -1783.86,5192.91 -1781.37,5192.91 ccw(c-1781.37,5198.91) -1775.38,5198.91 -1775.38,5211.92 cw(c-1769.39,5211.92) -1769.39,5217.91 -1751.41,5217.91 cw(c-1751.41,5211.92) -1745.42,5211.92 -1745.42,5195.19 ccw(c-1739.42,5195.19) -1739.42,5189.2 -1721.45,5189.2 ccw(c-1721.45,5195.19) -1715.45,5195.19 -1715.45,5211.92 cw(c-1709.46,5211.92) -1709.46,5217.91 -1691.48,5217.91 cw(c-1691.48,5211.92) -1685.49,5211.92 -1685.49,5195.19 ccw(c-1679.5,5195.19) -1679.5,5189.2 -1661.52,5189.2 ccw(c-1661.52,5195.19) -1655.53,5195.19 -1655.53,5211.92 cw(c-1649.54,5211.92) -1649.54,5217.91 -1631.56,5217.91 cw(c-1631.56,5211.92) -1625.57,5211.92 -1625.57,5195.19 ccw(c-1619.57,5195.19) -1619.57,5189.2 -1601.6,5189.2 ccw(c-1601.6,5195.19) -1595.6,5195.19 -1595.6,5211.92 cw(c-1589.61,5211.92) -1589.61,5217.91 -1571.63,5217.91 cw(c-1571.63,5211.92) -1565.64,5211.92 -1565.64,5195.19 ccw(c-1559.65,5195.19) -1559.65,5189.2 -1541.67,5189.2 ccw(c-1541.67,5195.19) -1535.68,5195.19 -1535.68,5211.92 cw(c-1529.68,5211.92) -1529.68,5217.91 -1511.71,5217.91 cw(c-1511.71,5211.92) -1505.71,5211.92 -1505.71,5195.19 ccw(c-1499.72,5195.19) -1499.72,5189.2 -1481.74,5189.2 ccw(c-1481.74,5195.19) -1475.75,5195.19 -1475.75,5211.92 cw(c-1469.76,5211.92) -1469.76,5217.91 -1451.78,5217.91 cw(c-1451.78,5211.92) -1445.79,5211.92 -1445.79,5195.19 ccw(c-1439.79,5195.19) -1439.79,5189.2 -1421.82,5189.2 ccw(c-1421.82,5195.19) -1415.82,5195.19 -1415.82,5211.92 cw(c-1409.83,5211.92) -1409.83,5217.91 -1391.85,5217.91 cw(c-1391.85,5211.92) -1385.86,5211.92 -1385.86,5198.91 ccw(c-1379.87,5198.91) -1379.87,5192.91 -1337.58,5192.91 -1330.69,5192.91 -1031.48,5492.13 -733.49,5492.13 -677.12,5435.76 J6.24@-677.12,5399.01
PORTC_S20: J6.25 MC3.43 | length 3382.7
  L1-TOP w4.96: v1(-2332.68,3931.1) MC3.43@-2332.68,3979.92
  L6-BOT w4.96: v1(-2332.68,3931.1) -2332.68,3958.66 -2336.04,3962.03 -2336.04,4374.99 -1795.17,4915.87 -1793.41,4917.62 ccw(c-1797.65,4921.86) -1793.41,4926.1 -1817.82,4950.51 cw(c-1813.59,4954.75) -1817.82,4958.98 -1805.11,4971.7 cw(c-1800.87,4967.46) -1796.64,4971.7 -1771.87,4946.93 ccw(c-1767.63,4951.17) -1763.39,4946.93 -1750.68,4959.64 ccw(c-1754.92,4963.88) -1750.68,4968.12 -1775.45,4992.88 cw(c-1771.21,4997.12) -1775.45,5001.36 -1762.74,5014.07 cw(c-1758.5,5009.83) -1754.26,5014.07 -1729.5,4989.3 ccw(c-1725.26,4993.54) -1721.02,4989.3 -1708.31,5002.02 ccw(c-1712.55,5006.25) -1708.31,5010.49 -1733.07,5035.26 cw(c-1728.84,5039.5) -1733.07,5043.73 -1720.36,5056.45 cw(c-1716.13,5052.21) -1711.89,5056.45 -1687.12,5031.68 ccw(c-1682.88,5035.92) -1678.65,5031.68 -1665.93,5044.39 ccw(c-1670.17,5048.63) -1665.93,5052.87 -1690.7,5077.63 cw(c-1686.46,5081.87) -1690.7,5086.11 -1677.99,5098.82 cw(c-1673.75,5094.58) -1669.51,5098.82 -1644.75,5074.05 ccw(c-1640.51,5078.29) -1636.27,5074.05 -1623.56,5086.76 ccw(c-1627.8,5091) -1623.56,5095.24 -1648.33,5120.01 cw(c-1644.09,5124.24) -1648.33,5128.48 -1635.61,5141.19 cw(c-1631.38,5136.96) -1627.14,5141.19 -1602.37,5116.43 ccw(c-1598.14,5120.66) -1593.9,5116.43 -1581.19,5129.14 ccw(c-1585.42,5133.38) -1581.19,5137.61 -1605.95,5162.38 cw(c-1601.72,5166.62) -1605.95,5170.86 -1593.24,5183.57 cw(c-1589,5179.33) -1584.77,5183.57 -1560,5158.8 ccw(c-1555.76,5163.04) -1551.52,5158.8 -1538.81,5171.51 ccw(c-1543.05,5175.75) -1538.81,5179.99 -1563.58,5204.75 cw(c-1559.34,5208.99) -1563.58,5213.23 -1550.87,5225.94 cw(c-1546.63,5221.7) -1542.39,5225.94 -1517.62,5201.17 ccw(c-1513.39,5205.41) -1509.15,5201.17 -1496.44,5213.89 ccw(c-1500.68,5218.12) -1496.44,5222.36 -1515.06,5240.98 cw(c-1510.82,5245.22) -1515.06,5249.45 -1502.34,5262.17 cw(c-1498.11,5257.93) -1493.87,5262.17 -1475.61,5243.9 ccw(c-1471.37,5248.14) -1467.13,5243.9 -1436.23,5274.81 -1420.91,5290.12 -1214.55,5290.12 -1117.54,5387.13 -1117.54,5402.51 -1048.67,5471.38 -1031.89,5471.38 -1004.51,5498.77 -1004.51,5513.21 -987.31,5530.41 -749.43,5530.41 -729.08,5550.76 -729.08,5559.04 -708.72,5579.4 v2(-708.72,5667.97)
PORTC_S21: J6.26 MC3.42 | length 3384.6
  L1-TOP w4.96: v1@-2405.51,3631.89 v1(-2405.51,3633.86) -2352.36,3687.01 MC3.42@-2352.36,3736.61
  L6-BOT w4.96: v1(-2405.51,3633.86) -2405.51,3692.38 -2232.28,3865.61 -2232.28,4005.04 -2248.03,4020.79 -2248.03,4196.85 -2240.16,4204.72 -2238.4,4206.48 ccw(c-2242.64,4210.72) -2238.4,4214.95 -2246.52,4223.07 cw(c-2242.28,4227.3) -2246.52,4231.54 -2233.8,4244.25 cw(c-2229.57,4240.02) -2225.33,4244.25 -2199.54,4218.46 ccw(c-2195.3,4222.7) -2191.06,4218.46 -2178.35,4231.18 ccw(c-2182.59,4235.41) -2178.35,4239.65 -2205.09,4266.39 cw(c-2200.85,4270.62) -2205.09,4274.86 -2192.37,4287.57 cw(c-2188.14,4283.34) -2183.9,4287.57 -2157.16,4260.84 ccw(c-2152.93,4265.07) -2148.69,4260.84 -2135.98,4273.55 ccw(c-2140.21,4277.79) -2135.98,4282.02 -2162.71,4308.76 cw(c-2158.48,4313) -2162.71,4317.24 -2150,4329.95 cw(c-2145.76,4325.71) -2141.53,4329.95 -2114.79,4303.21 ccw(c-2110.55,4307.45) -2106.31,4303.21 -2093.6,4315.92 ccw(c-2097.84,4320.16) -2093.6,4324.4 -2120.34,4351.13 cw(c-2116.1,4355.37) -2120.34,4359.61 -2107.63,4372.32 cw(c-2103.39,4368.08) -2099.15,4372.32 -2072.42,4345.59 ccw(c-2068.18,4349.82) -2063.94,4345.59 -2051.23,4358.3 ccw(c-2055.47,4362.53) -2051.23,4366.77 -2077.96,4393.51 cw(c-2073.73,4397.75) -2077.96,4401.98 -2065.25,4414.7 cw(c-2061.01,4410.46) -2056.78,4414.7 -2030.04,4387.96 ccw(c-2025.8,4392.2) -2021.57,4387.96 -2008.85,4400.67 ccw(c-2013.09,4404.91) -2008.85,4409.15 -2035.59,4435.88 cw(c-2031.35,4440.12) -2035.59,4444.36 -2022.88,4457.07 cw(c-2018.64,4452.83) -2014.4,4457.07 -1994.92,4437.59 ccw(c-1990.68,4441.82) -1986.44,4437.59 -1973.73,4450.3 ccw(c-1977.97,4454.54) -1973.73,4458.77 -1975.68,4460.72 cw(c-1971.45,4464.96) -1975.68,4469.2 -1940.94,4503.94 -1241.37,5203.51 -1176.7,5203.51 -1060.27,5319.93 -739.12,5319.93 -708.72,5350.33 v2(-708.72,5442.37)
PORTC_S22: J6.27 MC3.34 | length 3383.5
  L1-TOP w4.96: MC3.34@-2431.1,3736.61 -2431.23,3736.74 -2431.23,3772.01 -2392.45,3810.78 -2392.45,3820.14 v1(-2389.76,3822.83)
  L6-BOT w4.96: v1(-2389.76,3822.83) -2389.76,3866.21 -2393.7,3870.14 -2393.7,3909.45 -2353,3950.15 -2353,4402.9 -2340.55,4415.35 -2338.8,4417.11 ccw(c-2343.03,4421.35) -2338.8,4425.58 -2381.11,4467.9 cw(c-2376.87,4472.14) -2381.11,4476.37 -2368.4,4489.09 cw(c-2364.16,4484.85) -2359.92,4489.09 -2313.11,4442.27 ccw(c-2308.87,4446.51) -2304.63,4442.27 -2291.92,4454.98 ccw(c-2296.16,4459.22) -2291.92,4463.46 -2338.74,4510.27 cw(c-2334.5,4514.51) -2338.74,4518.75 -2326.02,4531.46 cw(c-2321.79,4527.22) -2317.55,4531.46 -2270.73,4484.64 ccw(c-2266.5,4488.88) -2262.26,4484.64 -2249.55,4497.36 ccw(c-2253.78,4501.59) -2249.55,4505.83 -2296.36,4552.65 cw(c-2292.13,4556.88) -2296.36,4561.12 -2283.65,4573.83 cw(c-2279.41,4569.6) -2275.18,4573.83 -2228.36,4527.02 ccw(c-2224.12,4531.25) -2219.88,4527.02 -2207.17,4539.73 ccw(c-2211.41,4543.97) -2207.17,4548.2 -2243.38,4584.41 cw(c-2239.14,4588.65) -2243.38,4592.89 -2230.67,4605.6 cw(c-2226.43,4601.36) -2222.2,4605.6 -2190.49,4573.89 ccw(c-2186.25,4578.13) -2182.01,4573.89 -2139.76,4616.14 -1870.08,4885.83 -1870.08,4937.01 -1500,5307.09 -1221.57,5307.09 -1134.5,5394.16 -1134.5,5409.54 -998.61,5545.43 -793.97,5545.43 -758.14,5581.25 v2(-740.22,5581.25)
PORTC_S23: J6.28 MC3.51 | length 3382.7
  L1-TOP w4.96: v1(-2253.94,3931.1) MC3.51@-2253.94,3979.92
  L6-BOT w4.96: v1(-2253.94,3931.1) -2253.94,4002.7 -2267.72,4016.48 -2267.72,4236.22 -1958.66,4545.28 -1956.91,4547.03 ccw(c-1961.14,4551.27) -1956.91,4555.51 -1960.18,4558.78 cw(c-1955.94,4563.02) -1960.18,4567.25 -1947.47,4579.97 cw(c-1943.23,4575.73) -1938.99,4579.97 -1918.19,4559.16 ccw(c-1913.95,4563.4) -1909.71,4559.16 -1897,4571.87 ccw(c-1901.24,4576.11) -1897,4580.35 -1917.81,4601.15 cw(c-1913.57,4605.39) -1917.81,4609.63 -1905.09,4622.34 cw(c-1900.86,4618.1) -1896.62,4622.34 -1875.81,4601.53 ccw(c-1871.58,4605.77) -1867.34,4601.53 -1854.63,4614.25 ccw(c-1858.86,4618.48) -1854.63,4622.72 -1875.43,4643.53 cw(c-1871.19,4647.76) -1875.43,4652 -1862.72,4664.71 cw(c-1858.48,4660.48) -1854.25,4664.71 -1833.44,4643.91 ccw(c-1829.2,4648.14) -1824.96,4643.91 -1812.25,4656.62 ccw(c-1816.49,4660.86) -1812.25,4665.09 -1833.06,4685.9 cw(c-1828.82,4690.14) -1833.06,4694.38 -1820.35,4707.09 cw(c-1816.11,4702.85) -1811.87,4707.09 -1791.06,4686.28 ccw(c-1786.83,4690.52) -1782.59,4686.28 -1769.88,4698.99 ccw(c-1774.11,4703.23) -1769.88,4707.47 -1790.68,4728.28 cw(c-1786.45,4732.51) -1790.68,4736.75 -1777.97,4749.46 cw(c-1773.73,4745.23) -1769.5,4749.46 -1748.69,4728.66 ccw(c-1744.45,4732.89) -1740.22,4728.66 -1727.5,4741.37 ccw(c-1731.74,4745.61) -1727.5,4749.84 -1748.31,4770.65 cw(c-1744.07,4774.89) -1748.31,4779.12 -1735.6,4791.84 cw(c-1731.36,4787.6) -1727.12,4791.84 -1706.32,4771.03 ccw(c-1702.08,4775.27) -1697.84,4771.03 -1685.13,4783.74 ccw(c-1689.37,4787.98) -1685.13,4792.22 -1705.94,4813.02 cw(c-1701.7,4817.26) -1705.94,4821.5 -1693.22,4834.21 cw(c-1688.99,4829.97) -1684.75,4834.21 ; -1684.75,4834.21 -1663.94,4813.4 ccw(c-1659.7,4817.64) -1655.47,4813.4 -1642.75,4826.12 ccw(c-1646.99,4830.35) -1642.75,4834.59 -1663.56,4855.4 cw(c-1659.32,4859.64) -1663.56,4863.87 -1650.85,4876.58 cw(c-1646.61,4872.35) -1642.37,4876.58 -1621.57,4855.78 ccw(c-1617.33,4860.02) -1613.09,4855.78 -1600.38,4868.49 ccw(c-1604.62,4872.73) -1600.38,4876.96 -1621.19,4897.77 cw(c-1616.95,4902.01) -1621.19,4906.25 -1608.48,4918.96 cw(c-1604.24,4914.72) -1600,4918.96 -1579.19,4898.15 ccw(c-1574.96,4902.39) -1570.72,4898.15 -1558.01,4910.86 ccw(c-1562.24,4915.1) -1558.01,4919.34 -1578.81,4940.15 cw(c-1574.58,4944.38) -1578.81,4948.62 -1566.1,4961.33 cw(c-1561.86,4957.1) -1557.63,4961.33 -1536.82,4940.53 ccw(c-1532.58,4944.76) -1528.34,4940.53 -1515.63,4953.24 ccw(c-1519.87,4957.48) -1515.63,4961.71 -1536.44,4982.52 cw(c-1532.2,4986.76) -1536.44,4990.99 -1523.73,5003.71 cw(c-1519.49,4999.47) -1515.25,5003.71 -1494.45,4982.9 ccw(c-1490.21,4987.14) -1485.97,4982.9 -1473.26,4995.61 ccw(c-1477.5,4999.85) -1473.26,5004.09 -1494.07,5024.89 cw(c-1489.83,5029.13) -1494.07,5033.37 -1481.35,5046.08 cw(c-1477.12,5041.84) -1472.88,5046.08 -1452.07,5025.27 ccw(c-1447.83,5029.51) -1443.6,5025.27 -1430.88,5037.99 ccw(c-1435.12,5042.22) -1430.88,5046.46 -1451.69,5067.27 cw(c-1447.45,5071.51) -1451.69,5075.74 -1438.98,5088.46 cw(c-1434.74,5084.22) -1430.5,5088.46 -1409.7,5067.65 ccw(c-1405.46,5071.89) -1401.22,5067.65 -1388.51,5080.36 ccw(c-1392.75,5084.6) -1388.51,5088.84 -1409.32,5109.64 cw(c-1405.08,5113.88) -1409.32,5118.12 -1396.61,5130.83 cw(c-1392.37,5126.59) -1388.13,5130.83 -1367.32,5110.02 ccw(c-1363.09,5114.26) -1358.85,5110.02 -1346.14,5122.73 ccw(c-1350.37,5126.97) -1346.14,5131.21 -1364.62,5149.69 cw(c-1360.38,5153.93) -1364.62,5158.17 -1351.91,5170.88 cw(c-1347.67,5166.64) -1343.43,5170.88 -1342.48,5169.93 ccw(c-1338.24,5174.17) -1334.01,5169.93 -1297.24,5206.69 -1283.46,5220.47 -1187.57,5220.47 -1068.43,5339.62 -756.26,5339.62 v2(-740.22,5355.65)
PORTC_S24: J6.29 MC3.39 | length 3558.7
  L1-TOP w4.96: MC3.39@-2372.05,3979.92 -2371.33,3980.63 -2371.33,4703.95 -2072.8,5002.49 -2049.86,5025.43 cw(c-2045.62,5021.19) -2041.38,5025.43 -2033.58,5017.62 ccw(c-2029.34,5021.86) -2025.1,5017.62 -2012.39,5030.33 ccw(c-2016.63,5034.57) -2012.39,5038.81 -2020.2,5046.62 cw(c-2015.96,5050.85) -2020.2,5055.09 -2007.48,5067.8 cw(c-2003.25,5063.57) -1999.01,5067.8 -1991.2,5060 ccw(c-1986.96,5064.23) -1982.73,5060 -1970.01,5072.71 ccw(c-1974.25,5076.95) -1970.01,5081.18 -1977.82,5088.99 cw(c-1973.58,5093.23) -1977.82,5097.47 -1965.11,5110.18 cw(c-1960.87,5105.94) -1956.64,5110.18 -1948.83,5102.37 ccw(c-1944.59,5106.61) -1940.35,5102.37 -1927.64,5115.08 ccw(c-1931.88,5119.32) -1927.64,5123.56 -1935.45,5131.37 cw(c-1931.21,5135.6) -1935.45,5139.84 -1922.74,5152.55 cw(c-1918.5,5148.32) -1914.26,5152.55 -1906.45,5144.74 ccw(c-1902.22,5148.98) -1897.98,5144.74 -1885.27,5157.46 ccw(c-1889.5,5161.69) -1885.27,5165.93 -1893.07,5173.74 cw(c-1888.84,5177.98) -1893.07,5182.21 -1840.52,5234.77 -1815.45,5259.84 -1796.26,5259.84 -1793.78,5259.84 ccw(c-1793.78,5265.84) -1787.78,5265.84 -1787.78,5278.85 cw(c-1781.79,5278.85) -1781.79,5284.84 -1763.81,5284.84 cw(c-1763.81,5278.85) -1757.82,5278.85 -1757.82,5240.87 ccw(c-1751.83,5240.87) -1751.83,5234.88 -1733.85,5234.88 ccw(c-1733.85,5240.87) -1727.86,5240.87 -1727.86,5278.85 cw(c-1721.87,5278.85) -1721.87,5284.84 -1703.89,5284.84 cw(c-1703.89,5278.85) -1697.9,5278.85 -1697.9,5240.87 ccw(c-1691.9,5240.87) -1691.9,5234.88 -1673.93,5234.88 ccw(c-1673.93,5240.87) -1667.93,5240.87 -1667.93,5278.85 cw(c-1661.94,5278.85) -1661.94,5284.84 -1643.96,5284.84 cw(c-1643.96,5278.85) -1637.97,5278.85 -1637.97,5240.87 ccw(c-1631.98,5240.87) -1631.98,5234.88 -1614,5234.88 ccw(c-1614,5240.87) -1608.01,5240.87 -1608.01,5278.85 cw(c-1602.01,5278.85) -1602.01,5284.84 -1584.04,5284.84 cw(c-1584.04,5278.85) -1578.04,5278.85 -1578.04,5240.87 ccw(c-1572.05,5240.87) -1572.05,5234.88 -1554.07,5234.88 ccw(c-1554.07,5240.87) -1548.08,5240.87 -1548.08,5278.85 cw(c-1542.09,5278.85) -1542.09,5284.84 -1524.11,5284.84 cw(c-1524.11,5278.85) -1518.12,5278.85 -1518.12,5240.87 ccw(c-1512.13,5240.87) -1512.13,5234.88 -1494.15,5234.88 ccw(c-1494.15,5240.87) -1488.15,5240.87 -1488.15,5278.85 cw(c-1482.16,5278.85) -1482.16,5284.84 -1464.18,5284.84 cw(c-1464.18,5278.85) -1458.19,5278.85 -1458.19,5240.87 ccw(c-1452.2,5240.87) -1452.2,5234.88 -1434.22,5234.88 ccw(c-1434.22,5240.87) -1428.23,5240.87 -1428.23,5278.85 cw(c-1422.24,5278.85) -1422.24,5284.84 -1404.26,5284.84 cw(c-1404.26,5278.85) -1398.27,5278.85 -1398.27,5240.87 ccw(c-1392.27,5240.87) -1392.27,5234.88 -1374.3,5234.88 ccw(c-1374.3,5240.87) -1368.3,5240.87 -1368.3,5278.85 cw(c-1362.31,5278.85) -1362.31,5284.84 -1344.33,5284.84 cw(c-1344.33,5278.85) -1338.34,5278.85 -1338.34,5265.84 ccw(c-1332.35,5265.84) -1332.35,5259.84 -1299.8,5259.84 -1294.82,5259.84 -1025.02,5529.64 -793.19,5529.64 -771.62,5551.21 J6.29@-771.62,5624.61
PORTC_S25: J6.30 MC3.40 | length 3381.7
  L1-TOP w4.96: v1@-2433.98,3634.86 -2372.05,3696.79 MC3.40@-2372.05,3736.61
  L6-BOT w4.96: v1(-2433.98,3633.86) -2433.07,3634.76 -2433.07,3692.91 -2295.28,3830.71 -2295.28,3885.46 -2271.65,3909.08 -2271.65,3996.43 -2285.14,4009.92 -2285.14,4266.28 -2277.68,4273.74 -2275.93,4275.5 ccw(c-2280.16,4279.74) -2275.93,4283.97 -2280.92,4288.96 cw(c-2276.68,4293.2) -2280.92,4297.44 -2268.2,4310.15 cw(c-2263.97,4305.91) -2259.73,4310.15 -2242.99,4293.41 ccw(c-2238.75,4297.65) -2234.51,4293.41 -2221.8,4306.12 ccw(c-2226.04,4310.36) -2221.8,4314.6 -2240.36,4333.16 cw(c-2236.12,4337.4) -2240.36,4341.63 -2227.65,4354.34 cw(c-2223.41,4350.11) -2219.17,4354.34 -2200.62,4335.79 ccw(c-2196.38,4340.02) -2192.14,4335.79 -2179.43,4348.5 ccw(c-2183.67,4352.74) -2179.43,4356.97 -2197.99,4375.53 cw(c-2193.75,4379.77) -2197.99,4384.01 -2185.28,4396.72 cw(c-2181.04,4392.48) -2176.8,4396.72 -2158.24,4378.16 ccw(c-2154,4382.4) -2149.77,4378.16 -2137.05,4390.87 ccw(c-2141.29,4395.11) -2137.05,4399.35 -2155.61,4417.91 cw(c-2151.38,4422.14) -2155.61,4426.38 -2142.9,4439.09 cw(c-2138.66,4434.86) -2134.43,4439.09 -2115.87,4420.53 ccw(c-2111.63,4424.77) -2107.39,4420.53 -2094.68,4433.25 ccw(c-2098.92,4437.48) -2094.68,4441.72 -2113.24,4460.28 cw(c-2109,4464.52) -2113.24,4468.75 -2100.53,4481.47 cw(c-2096.29,4477.23) -2092.05,4481.47 -2073.49,4462.91 ccw(c-2069.26,4467.15) -2065.02,4462.91 -2052.31,4475.62 ccw(c-2056.54,4479.86) -2052.31,4484.09 -2070.87,4502.65 cw(c-2066.63,4506.89) -2070.87,4511.13 -2058.15,4523.84 cw(c-2053.92,4519.6) -2049.68,4523.84 -2031.12,4505.28 ccw(c-2026.88,4509.52) -2022.64,4505.28 -2009.93,4517.99 ccw(c-2014.17,4522.23) -2009.93,4526.47 -2028.49,4545.03 cw(c-2024.25,4549.27) -2028.49,4553.5 -2015.78,4566.22 cw(c-2011.54,4561.98) -2007.3,4566.21 -2000.44,4559.35 ccw(c-1996.2,4563.59) -1991.97,4559.35 -1979.25,4572.06 ccw(c-1983.49,4576.3) -1979.25,4580.54 -1986.12,4587.4 cw(c-1981.88,4591.64) -1986.12,4595.88 -1973.41,4608.59 cw(c-1969.17,4604.35) -1964.93,4608.59 -1958.07,4601.72 ccw(c-1953.83,4605.96) -1949.59,4601.72 -1936.88,4614.44 ccw(c-1941.12,4618.67) -1936.88,4622.91 -1942.23,4628.26 cw(c-1937.99,4632.5) -1942.23,4636.73 -1929.51,4649.45 cw(c-1925.28,4645.21) -1921.04,4649.45 -1915.69,4644.1 ccw(c-1911.45,4648.34) -1907.22,4644.1 -1894.5,4656.81 ccw(c-1898.74,4661.05) -1894.5,4665.29 -1894.56,4665.34 cw(c-1890.32,4669.58) -1894.56,4673.82 -1881.85,4686.53 cw(c-1877.61,4682.29) -1873.37,4686.53 ccw(c-1869.13,4690.76) -1864.9,4686.53 -1839.34,4712.08 -1312.49,5238.93 -1193.76,5238.93 -1075.65,5357.04 -995.1,5357.04 -957.53,5394.62 -957.53,5442.2 -943.04,5456.69 -839.54,5456.69 -815.43,5432.59 -781.5,5432.59 v2(-771.72,5442.37)
PORTC_S26: J6.31 MC3.37 | length 3561.6
  L1-TOP w4.96: MC3.37@-2391.73,3979.92 -2391.73,4017.72 -2389.01,4020.44 -2389.01,4031.37 -2388.88,4031.5 -2388.88,4710.4 -1768.57,5330.71 -1750.03,5330.71 -1747.54,5330.71 ccw(c-1747.54,5336.7) -1741.55,5336.7 -1741.55,5372.06 cw(c-1735.56,5372.06) -1735.56,5378.05 -1717.58,5378.05 cw(c-1717.58,5372.06) -1711.59,5372.06 -1711.59,5311.7 ccw(c-1705.6,5311.7) -1705.6,5305.71 -1687.62,5305.71 ccw(c-1687.62,5311.7) -1681.63,5311.7 -1681.63,5372.06 cw(c-1675.63,5372.06) -1675.63,5378.05 -1657.66,5378.05 cw(c-1657.66,5372.06) -1651.66,5372.06 -1651.66,5311.7 ccw(c-1645.67,5311.7) -1645.67,5305.71 -1627.69,5305.71 ccw(c-1627.69,5311.7) -1621.7,5311.7 -1621.7,5372.06 cw(c-1615.71,5372.06) -1615.71,5378.05 -1597.73,5378.05 cw(c-1597.73,5372.06) -1591.74,5372.06 -1591.74,5311.7 ccw(c-1585.74,5311.7) -1585.74,5305.71 -1567.77,5305.71 ccw(c-1567.77,5311.7) -1561.77,5311.7 -1561.77,5372.06 cw(c-1555.78,5372.06) -1555.78,5378.05 -1537.8,5378.05 cw(c-1537.8,5372.06) -1531.81,5372.06 -1531.81,5311.7 ccw(c-1525.82,5311.7) -1525.82,5305.71 -1507.84,5305.71 ccw(c-1507.84,5311.7) -1501.85,5311.7 -1501.85,5372.06 cw(c-1495.86,5372.06) -1495.86,5378.05 -1477.88,5378.05 cw(c-1477.88,5372.06) -1471.88,5372.06 -1471.88,5311.7 ccw(c-1465.89,5311.7) -1465.89,5305.71 -1447.91,5305.71 ccw(c-1447.91,5311.7) -1441.92,5311.7 -1441.92,5372.06 cw(c-1435.93,5372.06) -1435.93,5378.05 -1417.95,5378.05 cw(c-1417.95,5372.06) -1411.96,5372.06 -1411.96,5311.7 ccw(c-1405.97,5311.7) -1405.97,5305.71 -1387.99,5305.71 ccw(c-1387.99,5311.7) -1382,5311.7 -1382,5336.77 cw(c-1376,5336.77) -1376,5342.76 -1358.03,5342.76 cw(c-1358.03,5336.77) -1352.03,5336.77 -1352.03,5336.7 ccw(c-1346.04,5336.7) -1346.04,5330.71 -1267.31,5330.71 -1251.16,5330.71 -1038.09,5543.78 -810.55,5543.78 -800.4,5553.93 -800.4,5569.04 -803.12,5571.76 J6.31@-803.12,5624.61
